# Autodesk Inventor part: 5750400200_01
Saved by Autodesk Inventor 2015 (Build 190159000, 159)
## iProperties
Created: 2020-07
Part Number: 5750400200_01
Checked By: TraceParts S.A.
Material: Generic
Catalog Web Link: www.traceparts.com
Document SubType Name: Modeling
Designer: TraceParts
Density: 1 g/cm^3
Appearance: Default
Company: TraceParts S.A.
Author: TraceParts
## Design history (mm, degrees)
feature "5750400200_01.ipt"
body "Solid1"
